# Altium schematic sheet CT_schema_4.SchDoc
size 356 x 211 mm
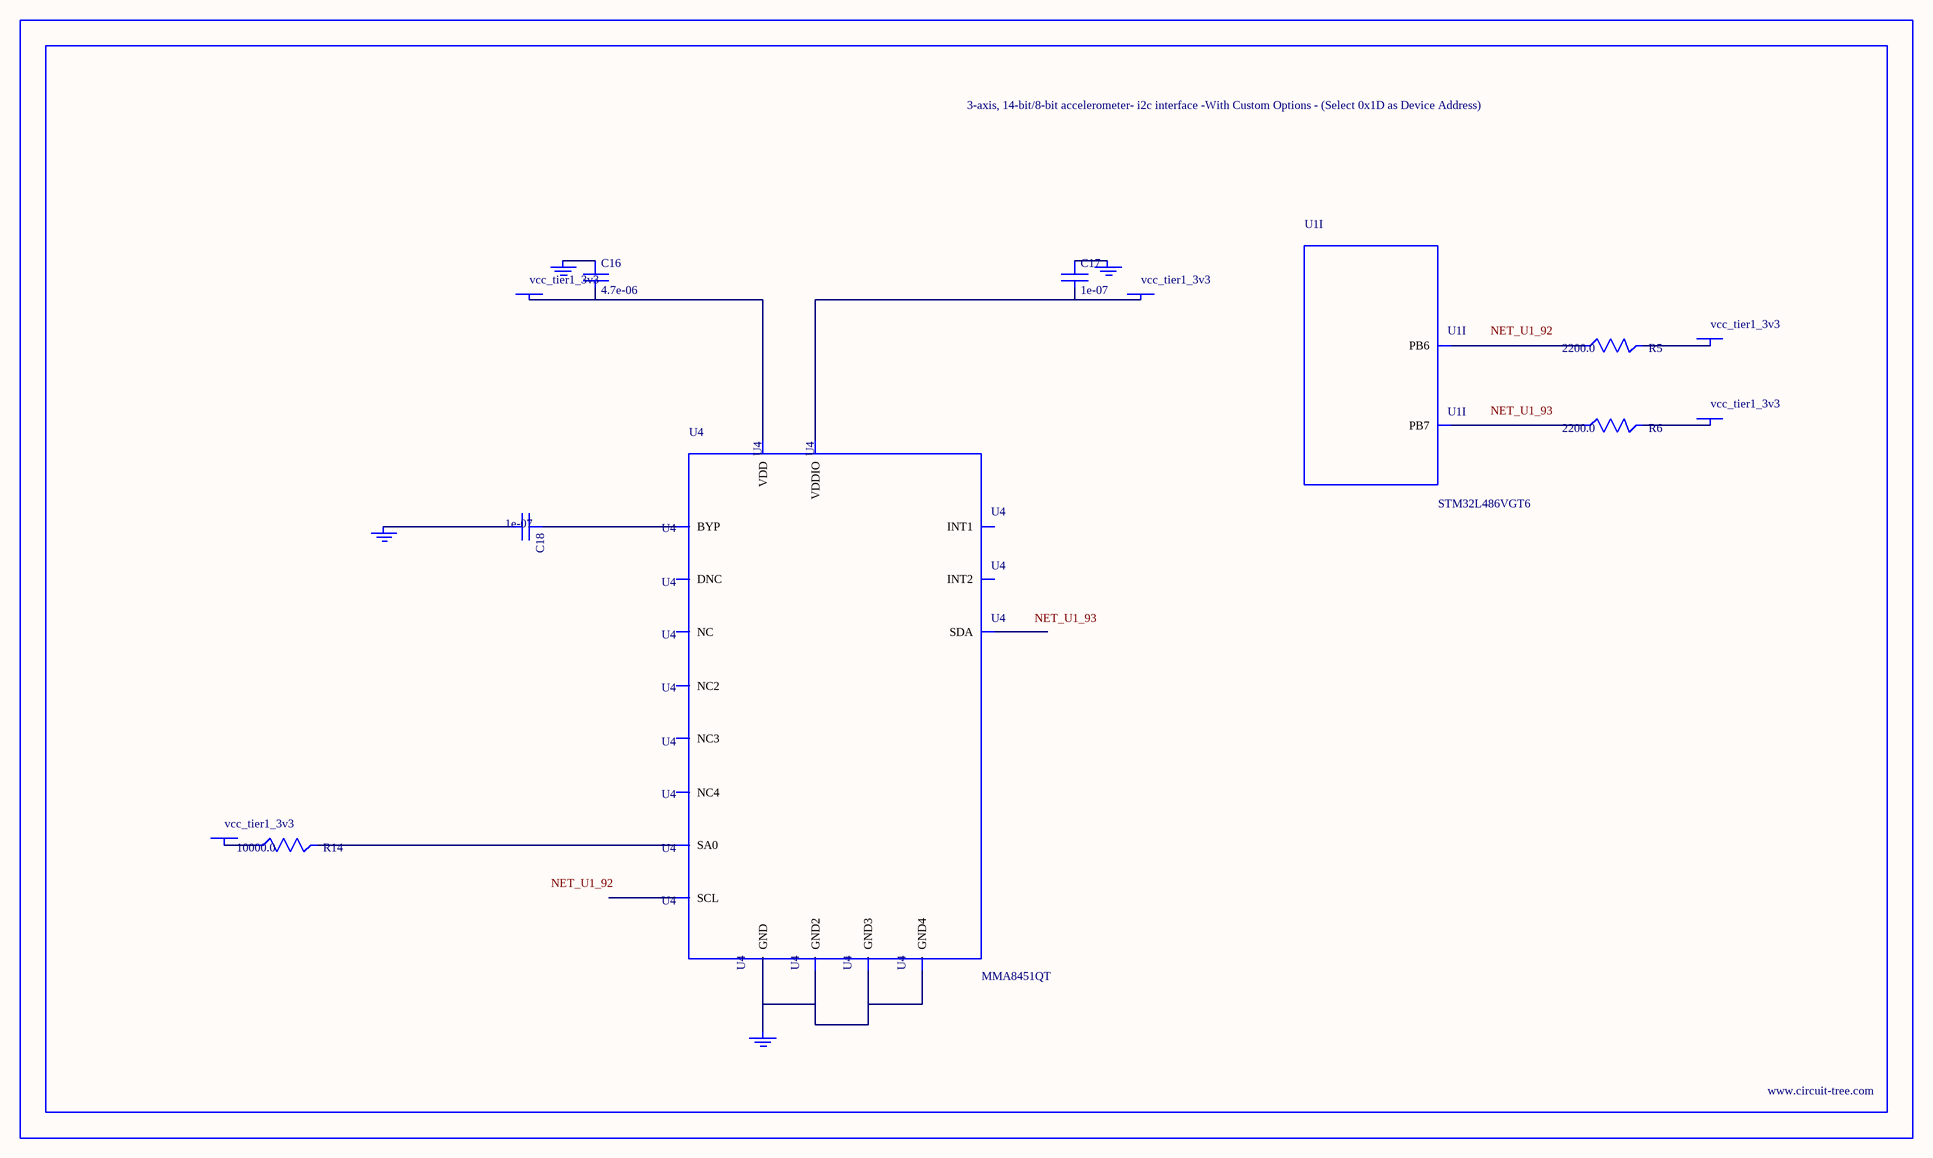
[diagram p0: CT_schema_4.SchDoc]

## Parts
BORDER3  (no value)
C16  4.7e-06  [C0805]
C17  1e-07  [C0402]
C18  1e-07  [C0402]
GND_INSTANCE_3_0  (no value)
GND_INSTANCE_3_1  (no value)
GND_INSTANCE_3_2  (no value)
GND_INSTANCE_3_3  (no value)
POWER_INSTANCE_3_0  vcc_tier1_3v3
POWER_INSTANCE_3_1  vcc_tier1_3v3
POWER_INSTANCE_3_2  vcc_tier1_3v3
POWER_INSTANCE_3_3  vcc_tier1_3v3
POWER_INSTANCE_3_4  vcc_tier1_3v3
R5  2200.0  [R0603]
R6  2200.0  [R0603]
R14  10000.0  [R0603]
U1  STM32L486VGT6  [LQFP100]  (part I of 10)
U4  MMA8451QT  [QFN-16]

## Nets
NetC16_1: C16.1 GND_INSTANCE_3_2.0(GND)
NetC16_2: C16.2 POWER_INSTANCE_3_2.0(PWR) U4.14(VDD)
NetC17_1: C17.1 GND_INSTANCE_3_0.0(GND)
NetC17_2: C17.2 POWER_INSTANCE_3_0.0(PWR) U4.1(VDDIO)
NetC18_1: C18.1 U4.2(BYP)
NetC18_2: C18.2 GND_INSTANCE_3_1.0(GND)
NetGND_INSTANCE_3_3_0: GND_INSTANCE_3_3.0(GND) U4.5(GND) U4.10(GND2) U4.12(GND3) U4.17(GND4)
NetPOWER_INSTANCE_3_1_0: POWER_INSTANCE_3_1.0(PWR) R14.1
NetPOWER_INSTANCE_3_3_0: POWER_INSTANCE_3_3.0(PWR) R5.2
NetPOWER_INSTANCE_3_4_0: POWER_INSTANCE_3_4.0(PWR) R6.2
NetR5_1: R5.1 U1.92(PB6)
NetR6_1: R6.1 U1.93(PB7)
NetR14_2: R14.2 U4.7(SA0)

Not connected (* = marked no-connect by the designer): U4 3(DNC) 4(SCL) 6(SDA) 8(NC) 9(INT2) 11(INT1) 13(NC2) 15(NC3) 16(NC4)

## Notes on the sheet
- Labels drawn without touching a wire or pin: NET_U1_92, NET_U1_93

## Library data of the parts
BORDER3 = BORDER_PAGE3
C16 = C0805C475K4RACTU
C17 C18 = C0402C104K3RACTU
GND_INSTANCE_3_0-GND_INSTANCE_3_3 = GND
POWER_INSTANCE_3_0-POWER_INSTANCE_3_4 = PWR
R5 R6 = RC0603JR-072K2L
R14 = RC0603JR-0710KL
